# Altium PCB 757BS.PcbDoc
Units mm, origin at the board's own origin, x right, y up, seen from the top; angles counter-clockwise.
Board outline 36.32 x 13.08 mm, 2 copper layers (Top Layer, Bottom Layer); 7 components, 34 nets, 106 pads, 47 vias.
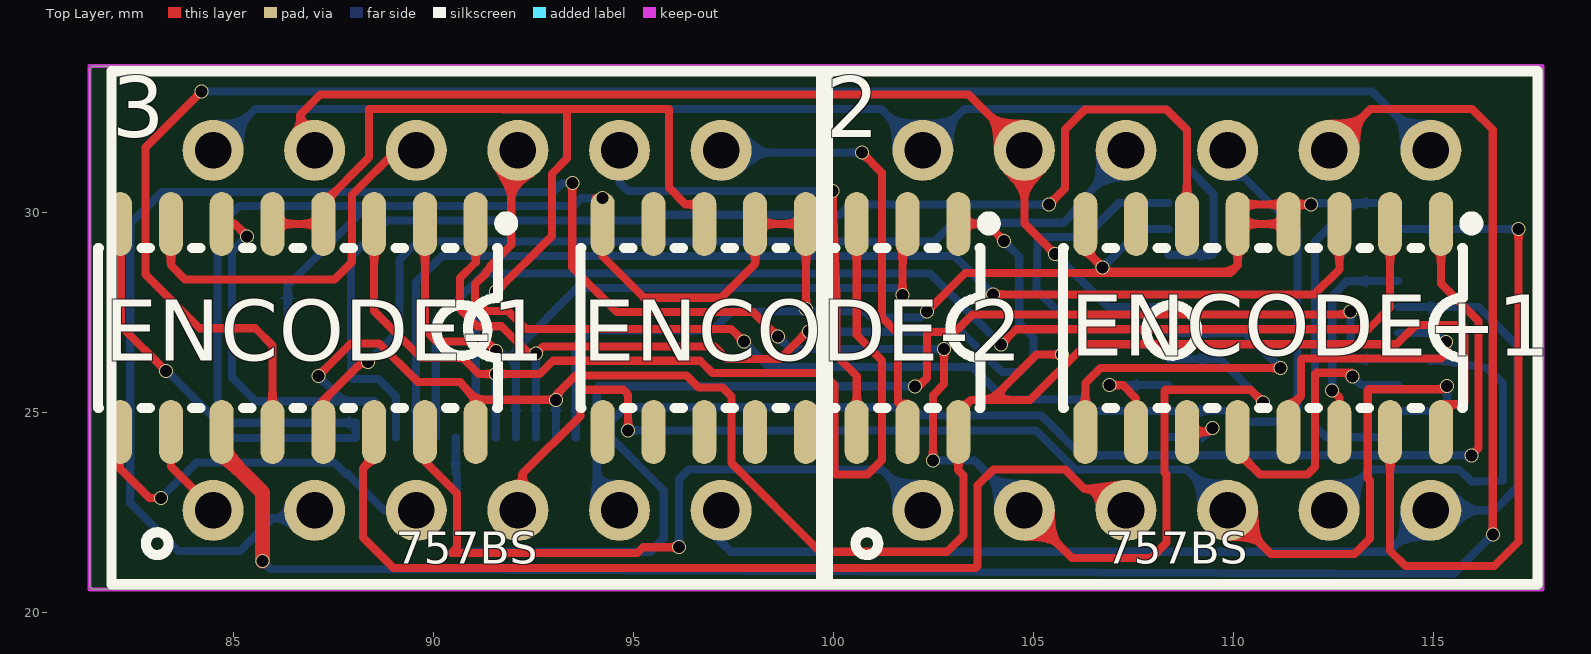
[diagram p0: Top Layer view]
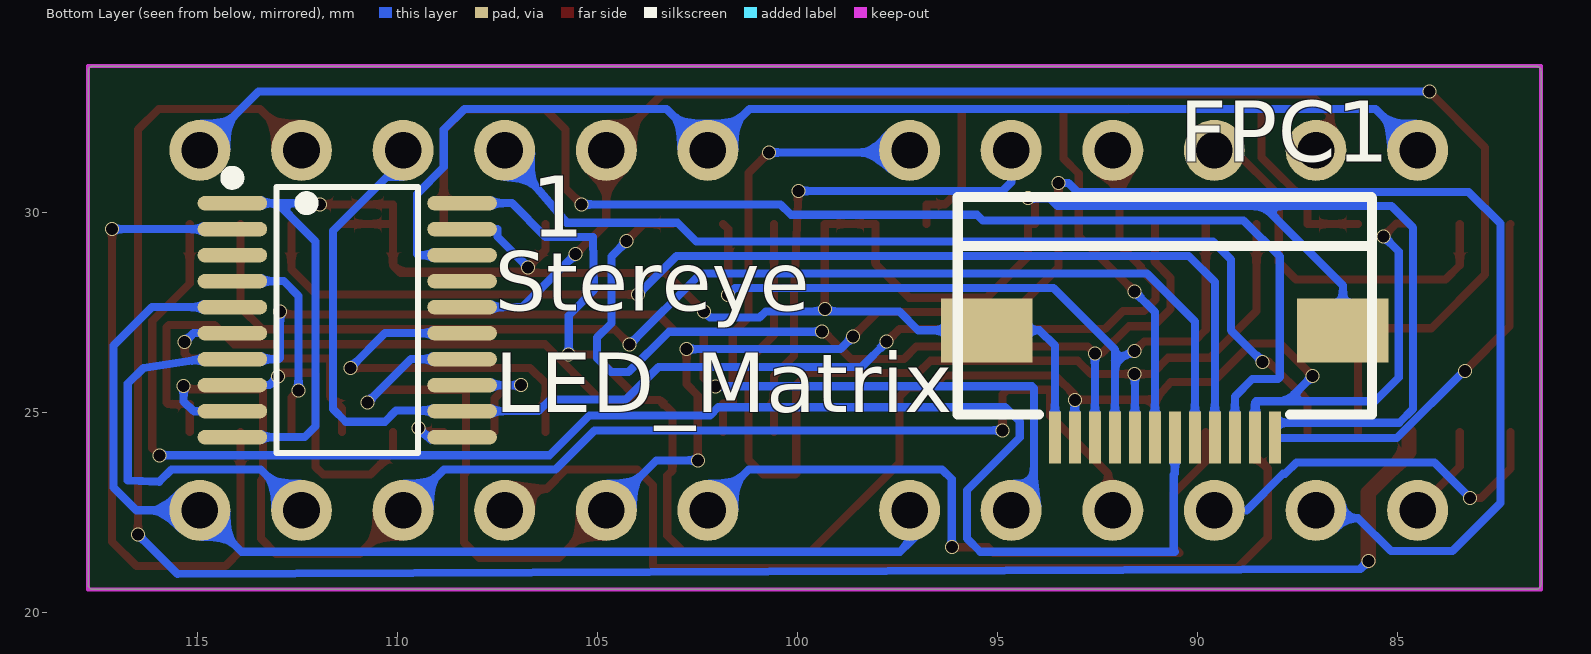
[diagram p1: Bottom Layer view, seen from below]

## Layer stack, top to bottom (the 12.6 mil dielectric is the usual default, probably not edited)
Top Solder: solder mask 0.0102, Solder Resist, Dk 3.5
Top Layer: signal copper 0.0356
Dielectric 1: dielectric 0.32, FR-4, Dk 4.8
Bottom Layer: signal copper 0.0356
Bottom Solder: solder mask 0.0102, Solder Resist, Dk 3.5

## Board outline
81.407,20.701 ccw(c81.534,20.701) 81.534,20.574 117.602,20.574 ccw(c117.602,20.701) 117.729,20.701 117.729,33.528 ccw(c117.602,33.528) 117.602,33.655 81.534,33.655 ccw(c81.534,33.528) 81.407,33.528

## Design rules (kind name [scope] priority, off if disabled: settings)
Clearance [All] p1: gap=0.152 ignorepadtopadclearanceinfootprint=FALSE
ComponentClearance [All] p1 off: gap=0.254 collisioncheckmode=3 verticalgap=0.254 showdistances=FALSE
PolygonConnect [All] p1: connectstyle=Relief reliefconductorwidth=0.254 reliefentries=4 polygonreliefangle="90 Angle" airgapwidth=0.254
RoutingVias [All] p1: holewidth=0.3 width=0.35 viastyle="Through Hole" minholewidth=0.3 minwidth=0.35 maxholewidth=0.711 maxwidth=1.27
SolderMaskExpansion [All] p1: expansion=0.102
Width [All] p1: maxlimit=1.27 minlimit=0.152 preferedwidth=0.203
29 further rules are at their usual default settings.

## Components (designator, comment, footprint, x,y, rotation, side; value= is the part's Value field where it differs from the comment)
1 "SN74HC240PWR" TSSOP-20 111.252,27.305 r270 bottom
2 "757BS LED Matrix" 757BS 108.458,27.051 r0 top
3 "757BS LED Matrix" 757BS 90.716,27.051 r0 top
ENCODE+1 "XL74LS138" SOP-16 110.744,27.111 r180 top
ENCODE-1 "XL74LS138" SOP-16 86.614,27.111 r180 top
ENCODE-2 "XL74LS138" SOP-16 98.679,27.111 r180 top
FPC1 "FPC-12P" FPC-0.5MM-12P 90.81,25.711 r180 bottom

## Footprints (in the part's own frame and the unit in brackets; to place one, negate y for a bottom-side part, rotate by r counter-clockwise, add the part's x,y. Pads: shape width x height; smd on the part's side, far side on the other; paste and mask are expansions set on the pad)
757BS [mil]
  round 60 hole 36: 1(-245,-177.17) 2(-145,-177.17) 3(-45,-177.17) 4(55,-177.17) 5(155,-177.17) 6(255,-177.17) 7(255,177.17) 8(155,177.17) 9(55,177.17) 10(-45,177.17) 11(-145,177.17) 12(-245,177.17)
  silkscreen extent -345,-250 360,255
FPC-0.5MM-12P [mm]
  rect 0.3x1.3 smd: 1(-2.751,-1.341) 2(-2.252,-1.341) 3(-1.751,-1.341) 4(-1.251,-1.341) 5(-0.751,-1.341) 6(-0.25,-1.341) 7(0.25,-1.341) 8(0.749,-1.341) 9(1.248,-1.341) 10(1.749,-1.341) 11(2.249,-1.341) 12(2.75,-1.341)
  rect 2.286x1.6 smd: 13(4.45,1.34) 14(-4.45,1.34)
  silkscreen extent -5.18,-0.76 5.18,4.67
SOP-16 [mm]
  oval 0.6x1.6 smd: 1(-4.445,-2.6) 2(-3.175,-2.6) 3(-1.905,-2.6) 4(-0.635,-2.6) 5(0.635,-2.6) 6(1.905,-2.6) 7(3.175,-2.6) 8(4.445,-2.6) 9(4.445,2.6) 10(3.175,2.6) 11(1.905,2.6) 12(0.635,2.6) 13(-0.635,2.6) 14(-1.905,2.6) 15(-3.175,2.6) 16(-4.445,2.6)
  silkscreen extent -5.36,-2.76 5,2
TSSOP-20 [mm]
  oval 0.364x1.742 smd: 1(-2.925,-2.871) 2(-2.275,-2.871) 3(-1.625,-2.871) 4(-0.975,-2.871) 5(-0.325,-2.871) 6(0.325,-2.871) 7(0.975,-2.871) 8(1.625,-2.871) 9(2.275,-2.871) 10(2.925,-2.871) 11(2.925,2.871) 12(2.275,2.871) 13(1.625,2.871) 14(0.975,2.871) 15(0.325,2.871) 16(-0.325,2.871) 17(-0.975,2.871) 18(-1.625,2.871) 19(-2.275,2.871) 20(-2.925,2.871)
  silkscreen extent -3.71,-3.02 3.33,1.77

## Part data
1: BOM_JLCPCB Part Class="Extended Part", BOM_Manufacturer="Texas Instruments"
2 3: library part 757BS
ENCODE+1 ENCODE-1 ENCODE-2: BOM_JLCPCB Part Class="Extended Part", BOM_Manufacturer=XINLUDA
FPC1: BOM_Manufacturer=JUSHUO, BOM_Manufacturer Part=AFC01-S12FCA-00

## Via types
v1: diameter 0.35, hole 0.3, Top Layer to Bottom Layer, 47 vias

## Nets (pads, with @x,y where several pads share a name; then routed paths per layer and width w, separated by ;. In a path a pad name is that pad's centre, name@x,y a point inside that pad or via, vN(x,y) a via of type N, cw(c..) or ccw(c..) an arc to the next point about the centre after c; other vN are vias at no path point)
A+: ENCODE+1.1 FPC1.7 | length 40.1
  Top Layer w0.203: ENCODE+1.1 115.189,28.219 116.126,27.282 116.126,24.102 v1(115.951,23.927)
  Bottom Layer w0.203: FPC1.7 90.56,23.47 90.589,23.44 90.589,21.539 90.564,21.514 95.428,21.514 95.758,21.844 95.758,23.053 94.44,24.371 94.44,24.765 94.804,25.129 101.975,25.129 102.187,24.917 105.202,24.917 106.192,23.927 v1(115.951,23.927)
A-: ENCODE-1.1 ENCODE-2.1 FPC1.3 | length 24.8
  Top Layer w0.203: ENCODE-1.1 91.059,28.753 90.666,28.36 90.666,27.584 91.098,27.152 91.706,27.152 92.391,26.467 v1(92.561,26.467) 92.739,26.645 97.027,26.645 97.336,26.336 98.66,26.336 v1@99.349,27.026 ; ENCODE-2.1 103.842,29.711 v1(104.267,29.286)
  Bottom Layer w0.203: FPC1.3 v1(92.561,26.467) ; v1@99.349,27.026 99.359,27.016 103.21,27.016 104.216,26.01 104.661,26.01 105.004,26.352 105.004,26.873 104.648,27.229 104.648,28.892 104.267,29.273 v1(104.267,29.286)
  other v1: 99.389,27.026
B+: ENCODE+1.2 FPC1.8 | length 30.5
  Top Layer w0.203: v1(104.191,26.695) 104.572,27.076 113.373,27.076 113.919,27.622 ENCODE+1.2
  Bottom Layer w0.203: FPC1.8 90.061,27.272 91.262,28.473 102.413,28.473 v1(104.191,26.695)
B-: ENCODE-1.2 ENCODE-2.2 FPC1.4 | length 19.6
  Top Layer w0.203: ENCODE-1.2 89.789,27.066 90.083,26.772 91.327,26.772 v1(91.568,26.531) ; v1(101.727,27.94) 101.727,29.584 ENCODE-2.2
  Bottom Layer w0.203: v1(91.568,26.531) 92.061,26.299 ; FPC1.4 92.061,26.299 ; v1(101.727,27.94) 101.562,28.105 93.593,28.105 92.061,26.573 92.061,26.299
BS+1: 1.18 2.12 3.12 | length 30.9
  Bottom Layer w0.203: 3.12@84.102,31.143 85.547,32.588 101.198,32.588 2.12 103.272,32.588 108.318,32.588 108.839,32.067 108.839,31.13 109.506,30.463 109.506,28.956 109.48,28.93 1.18
BS+2: 1.16 2.11 3.11 | length 26.1
  Top Layer w0.203: 3.11@86.677,31.551 86.677,32.448 87.173,32.944 103.382,32.944 2.11 104.775,29.723 v1(105.542,28.956)
  Bottom Layer w0.203: v1(105.542,28.956) 106.868,27.63 1.16
BS+3: 1.14 2.2 3.2 | length 55.1
  Top Layer w0.203: v1(93.472,30.734) 93.472,28.626 94.587,27.511 97.993,27.511 v1(98.611,26.894) ; v1(102.489,23.8) 102.489,25.425 102.768,25.705 v1(102.768,26.581) ; 2.2 105.965,21.361 107.95,21.361 108.331,21.742 108.331,23.444 108.28,23.495 108.28,25.54 108.306,25.565 110.427,25.565 v1(110.744,25.248)
  Bottom Layer w0.203: 3.2@86.868,22.352 85.979,22.352 85.162,21.535 83.621,21.535 82.423,22.733 82.423,29.718 83.215,30.51 92.994,30.51 93.218,30.734 v1(93.472,30.734) ; v1(98.611,26.894) 98.923,26.581 v1(102.768,26.581) ; v1(102.489,23.8) 103.526,23.8 2.2 ; 1.14 109.662,26.33 v1(110.744,25.248)
BS+4: 1.12 2.9 3.9 | length 33.6
  Top Layer w0.203: 3.9@91.613,31.551 91.948,31.216 91.948,29.181 91.415,28.648 91.415,28.606 91.313,28.504 91.313,28.473 91.044,28.204 91.044,27.825 91.335,27.534 91.862,27.534 92.312,27.083 97.447,27.083 v1(97.765,26.766)
  Bottom Layer w0.203: v1(97.765,26.766) 98.394,26.137 103.473,26.137 104.286,25.324 106.172,25.324 106.466,25.03 1.12 109.068,25.03 109.082,25.044 110.033,25.044 110.312,24.765 111.29,24.765 111.608,25.082 111.608,29.54 110.257,30.891 109.855,30.891 2.9
BS+5: 1.9 2.4 3.4 | length 33.2
  Top Layer w0.203: 3.4 92.23,22.667 92.23,23.467 93.675,24.913 93.675,25.54 93.701,25.565 94.75,25.565 94.869,25.446 v1(94.869,24.549) ; 2.4 110.943,21.463 113.03,21.463 113.411,21.844 113.411,23.292 113.36,23.343 113.36,25.552 113.386,25.578 115.265,25.578 v1(115.341,25.654)
  Bottom Layer w0.203: v1(94.869,24.549) 105.067,24.549 106.045,23.571 108.835,23.571 2.4 ; 1.9 115.098,25.03 115.341,25.273 v1(115.341,25.654)
BS+6: 1.7 2.5 3.5 | length 35.9
  Top Layer w0.203: v1(102.044,25.651) 102.133,25.651 102.339,25.857 102.339,26.975 102.375,27.01 103.042,27.01 103.482,27.45 112.861,27.45 v1(112.928,27.518)
  Bottom Layer w0.203: 3.5@94.183,22.551 94.084,22.65 94.084,25.603 94.132,25.651 v1(102.044,25.651) ; 2.5 113.415,23.571 115.646,23.571 115.951,23.266 116.738,23.292 116.738,25.717 116.345,26.111 114.884,26.33 1.7 112.954,26.33 112.928,26.355 v1(112.928,27.518)
BS+7: 1.5 2.6 3.6 | length 28.9
  Bottom Layer w0.203: 3.6@96.793,22.151 97.193,21.751 ; 3.6 97.193,21.751 ; 1.5 116.134,27.63 117.094,26.67 117.094,23.122 116.522,22.551 2.6 113.898,21.514 97.43,21.514 97.193,21.751
BS-1: 2.1 ENCODE-1.15 | length 17.5
  Top Layer w0.203: ENCODE-1.15 89.789,23.772 90.589,22.972 90.589,21.628 90.449,21.488 95.097,21.488 95.236,21.628 v1(96.139,21.628)
  Bottom Layer w0.203: v1@96.139,21.59 v1(96.139,21.628) 96.139,23.33 96.38,23.571 101.215,23.571 2.1
BS-2: 2.3 ENCODE-1.14 | length 24.8
  Top Layer w0.203: ENCODE-1.14 88.519,23.876 88.24,23.597 88.24,21.869 89.002,21.107 103.556,21.107 103.607,21.158 103.607,23.177 104,23.571 105.791,23.571 106.274,23.089 106.777,23.089 2.3
BS-3: 2.10 ENCODE-1.13 | length 24.6
  Top Layer w0.203: ENCODE-1.13 87.249,25.298 88.214,26.264 v1(88.367,26.264)
  Bottom Layer w0.203: v1(88.367,26.264) 89.154,27.051 89.154,28.819 89.608,29.273 102.527,29.273 102.994,29.741 105.767,29.741 2.10
BS-4: 2.7 ENCODE-1.12 | length 42.6
  Top Layer w0.203: v1(84.201,33.02) 82.804,31.623 82.804,28.448 84.15,27.102 85.547,27.102 85.979,26.67 ENCODE-1.12
  Bottom Layer w0.203: v1(84.201,33.02) 113.466,33.02 2.7
BS-5: 2.8 ENCODE-1.11 | length 49.8
  Top Layer w0.203: 2.8 113.432,32.588 115.964,32.588 116.484,32.067 v1(116.484,21.946)
  Top Layer w0.381: ENCODE-1.11 84.709,24.011 85.725,22.995 v1(85.725,21.285)
  Bottom Layer w0.203: v1(85.725,21.285) 85.923,21.086 115.499,20.961 v1(116.484,21.946)
BS-6: 3.1 ENCODE-1.10 | length 2.3
  Top Layer w0.203: ENCODE-1.10 83.439,23.647 84.201,22.885 3.1@84.201,22.551
BS-7: 3.3 ENCODE-1.9 | length 8.7
  Top Layer w0.203: ENCODE-1.9 82.169,23.597 82.906,22.86 v1(83.185,22.86)
  Bottom Layer w0.203: v1(83.185,22.86) 84.074,23.749 87.522,23.749 87.805,23.466 87.858,23.466 88.773,22.551
BS-8: 3.10 ENCODE-1.7 | length 9.6
  Top Layer w0.203: ENCODE-1.7 83.439,28.677 83.795,28.321 87.528,28.321 87.965,28.758 87.965,30.441 89.075,31.551 3.10
BS-9: 3.7 ENCODE-2.15 | length 11.1
  Top Layer w0.203: v1(100.711,31.496) 101.219,30.988 101.219,27.371 101.615,26.975 101.615,25.248 101.641,25.222 101.854,25.222 ENCODE-2.15
  Bottom Layer w0.203: 3.7 97.248,31.496 v1(100.711,31.496)
BS-10: 3.8 ENCODE-2.14 | length 12.4
  Top Layer w0.203: v1(99.974,30.535) 100.079,27.935 100.079,26.416 100.584,25.911 ENCODE-2.14
  Bottom Layer w0.203: 3.8 94.653,30.751 94.869,30.535 v1(99.974,30.535)
C+: ENCODE+1.3 FPC1.9 | length 29
  Top Layer w0.203: v1(103.988,27.946) 112.02,27.946 112.649,28.575 ENCODE+1.3
  Bottom Layer w0.203: FPC1.9 89.562,28.258 90.214,28.91 103.023,28.91 v1(103.988,27.946)
C-: ENCODE-1.3 ENCODE-2.3 FPC1.5 | length 26
  Top Layer w0.203: ENCODE-1.3 88.519,27.534 89.687,26.365 90.729,26.365 91.135,25.959 v1(91.567,25.959) 92.66,25.959 92.99,26.289 96.672,26.289 96.98,25.981 99.726,25.981 100.025,25.682 100.025,23.471 100.051,23.445 100.853,23.445 101.22,23.812 101.22,26.3 100.584,26.936 ENCODE-2.3
  Bottom Layer w0.203: FPC1.5 91.561,25.952 v1(91.567,25.959)
D-: ENCODE-1.4 ENCODE-1.5 ENCODE-2.6 FPC1.6 | length 26.4
  Top Layer w0.203: ENCODE-1.5 ENCODE-1.4 87.249,30.228 88.392,31.371 88.392,32.588 91.713,32.588 ; v1(91.567,28.016) 92.964,29.413 92.964,30.965 93.345,31.346 93.345,32.567 91.734,32.567 91.713,32.588 ; ENCODE-2.6 96.774,30.201 96.307,30.201 95.888,30.619 95.888,32.588 91.713,32.588
  Bottom Layer w0.203: FPC1.6 91.06,27.509 v1(91.567,28.016)
EN+: ENCODE+1.6 FPC1.10 | length 31.2
  Top Layer w0.203: v1(105.391,30.199) 105.791,30.599 105.791,32.067 106.291,32.567 108.331,32.567 108.839,32.059 ENCODE+1.6
  Bottom Layer w0.203: FPC1.10 89.061,25.4 88.627,25.835 87.986,25.835 87.938,25.883 87.938,28.892 88.845,29.799 95.363,29.799 95.504,29.94 100.162,29.94 100.42,30.199 v1(105.391,30.199)
GND: 1.1 1.10 1.19 ENCODE+1.4 ENCODE+1.5 ENCODE+1.8 ENCODE-1.8 ENCODE-2.4 ENCODE-2.5 ENCODE-2.8 FPC1.1 FPC1.12 FPC1.13 FPC1.14 | length 84.3
  Top Layer w0.203: ENCODE-1.8 82.194,29.686 82.194,27.153 v1(83.312,26.035) ; v1(94.234,30.353) 94.056,30.353 94.056,29.711 ENCODE-2.8 94.234,28.892 95.26,27.867 97.204,27.867 98.044,28.707 ENCODE-2.5 ENCODE-2.4 v1(99.314,27.584) v1@99.314,27.544 ; v1(102.337,27.525) 103.298,28.486 109.918,28.486 109.947,28.514 ; ENCODE+1.8 106.299,29.058 v1(106.731,28.626) 106.842,28.514 109.947,28.514 ; ENCODE+1.4 ENCODE+1.5 ; v1(111.938,30.201) 110.109,30.201 ENCODE+1.5 ; 109.947,28.514 110.109,28.677 ENCODE+1.5
  Bottom Layer w0.203: v1@83.325,26.048 85.014,24.359 88.061,24.359 FPC1.12 88.061,24.74 84.95,24.74 84.607,25.082 84.607,29.616 85.146,30.155 88.346,30.155 ; FPC1.13 86.36,28.169 88.346,30.155 ; FPC1.1 93.561,26.67 93.942,27.051 FPC1.14 96.976,27.051 97.449,27.525 v1@99.314,27.525 ; v1(94.234,30.353) 93.698,30.353 93.499,30.155 88.346,30.155 ; v1@99.314,27.544 v1@99.314,27.525 ; v1(102.337,27.525) 102.183,27.371 100.943,27.371 100.79,27.525 v1@99.314,27.525 ; v1(106.731,28.626) 107.496,29.391 107.496,29.58 1.19 ; v1(111.938,30.201) 111.967,30.23 113.005,30.23 ; 1.10 112.314,24.38 112.042,24.652 112.042,29.268 113.005,30.23 ; 1.1 113.005,30.23
LH0: 1.2 ENCODE+1.15 | length 17.4
  Top Layer w0.203: ENCODE+1.15 113.919,21.539 114.3,21.158 116.522,21.158 117.129,21.765 v1(117.129,29.58)
  Bottom Layer w0.203: 1.2 v1(117.129,29.58)
LH1: 1.4 ENCODE+1.14 | length 5.3
  Top Layer w0.203: v1(112.471,25.552) 112.649,25.375 ENCODE+1.14
  Bottom Layer w0.203: v1(112.471,25.552) 112.471,27.912 112.839,28.28 1.4
LH2: 1.6 ENCODE+1.13 | length 7.2
  Top Layer w0.203: ENCODE+1.13 111.379,25.095 111.687,25.403 111.687,26.314 111.719,26.347 115.196,26.347 115.316,26.467 v1(115.316,26.759)
  Bottom Layer w0.203: 1.6 115.095,26.98 v1(115.316,26.759)
LH3: 1.8 ENCODE+1.12 | length 7.3
  Top Layer w0.203: ENCODE+1.12 110.109,24.003 110.668,23.444 111.851,23.444 112.042,23.635 112.042,25.959 112.075,25.991 112.954,25.991 112.979,25.966 v1(112.979,25.895)
  Bottom Layer w0.203: v1(112.979,25.895) 113.194,25.68 1.8
LH4: 1.11 ENCODE+1.11 | length 1.9
  Top Layer w0.203: ENCODE+1.11 109.372,24.511 v1(109.474,24.613)
  Bottom Layer w0.203: 1.11 109.241,24.38 v1(109.474,24.613)
LH5: 1.13 ENCODE+1.10 | length 3.1
  Top Layer w0.203: v1(106.909,25.68) 107.238,25.68 107.569,25.349 ENCODE+1.10
  Bottom Layer w0.203: v1(106.909,25.68) 1.13
LH6: 1.15 ENCODE+1.9 | length 9.4
  Top Layer w0.203: ENCODE+1.9 106.299,25.73 106.68,26.111 v1(111.176,26.111)
  Bottom Layer w0.203: 1.15 110.307,26.98 v1(111.176,26.111)
VCC: 1.20 ENCODE+1.16 ENCODE-1.6 ENCODE-1.16 ENCODE-2.16 FPC1.2 FPC1.11 | length 62.1
  Top Layer w0.203: ENCODE-1.6 84.709,29.718 85.026,29.718 v1(85.344,29.4) ; v1(87.122,25.908) 87.935,26.721 88.646,26.721 89.611,25.756 90.672,25.756 91.059,25.314 ; ENCODE-1.16 91.059,25.314 ; v1(105.715,26.444) 105.08,26.444 103.947,25.311 ; ENCODE+1.16 115.189,25.209 115.732,25.209 115.77,25.248 115.77,27.127 115.71,27.188 114.567,27.188 114.081,26.702 106.311,26.702 104.919,25.311 103.947,25.311 ; 91.059,25.314 v1(93.062,25.314) 93.062,25.429 93.553,25.921 96.329,25.921 96.624,25.625 97.225,25.625 97.45,25.4 97.45,23.731 99.667,21.514 102.845,21.514 103.251,21.92 103.251,23.419 103.124,23.546 ENCODE-2.16 103.124,24.994 103.441,25.311 103.947,25.311
  Bottom Layer w0.203: v1(85.344,29.4) 84.963,29.019 84.963,25.87 85.557,25.276 87.754,25.276 ; v1(87.122,25.908) 87.754,25.276 ; FPC1.2 v1(93.062,25.314) v1@93.062,25.345 ; v1(105.715,26.444) 105.715,27.424 105.08,28.059 105.105,29.385 106.292,29.385 107.137,30.23 1.20 ; 87.754,25.276 88.532,25.276 ; 88.532,25.276 FPC1.11 88.561,25.248 88.532,25.276
pads on no net: 1.3 1.17 ENCODE+1.7 ENCODE-2.7 ENCODE-2.9 ENCODE-2.10 ENCODE-2.11 ENCODE-2.12 ENCODE-2.13

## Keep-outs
Keep-Out Layer:
  lines w0.1: 81.407,20.574 81.407,33.655 117.729,33.655 117.729,20.574 81.407,20.574

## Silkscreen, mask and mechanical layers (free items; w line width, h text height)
Bottom Overlay:
  text "Stereye / LED_Matrix" at 107.569,24.511 h2.54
